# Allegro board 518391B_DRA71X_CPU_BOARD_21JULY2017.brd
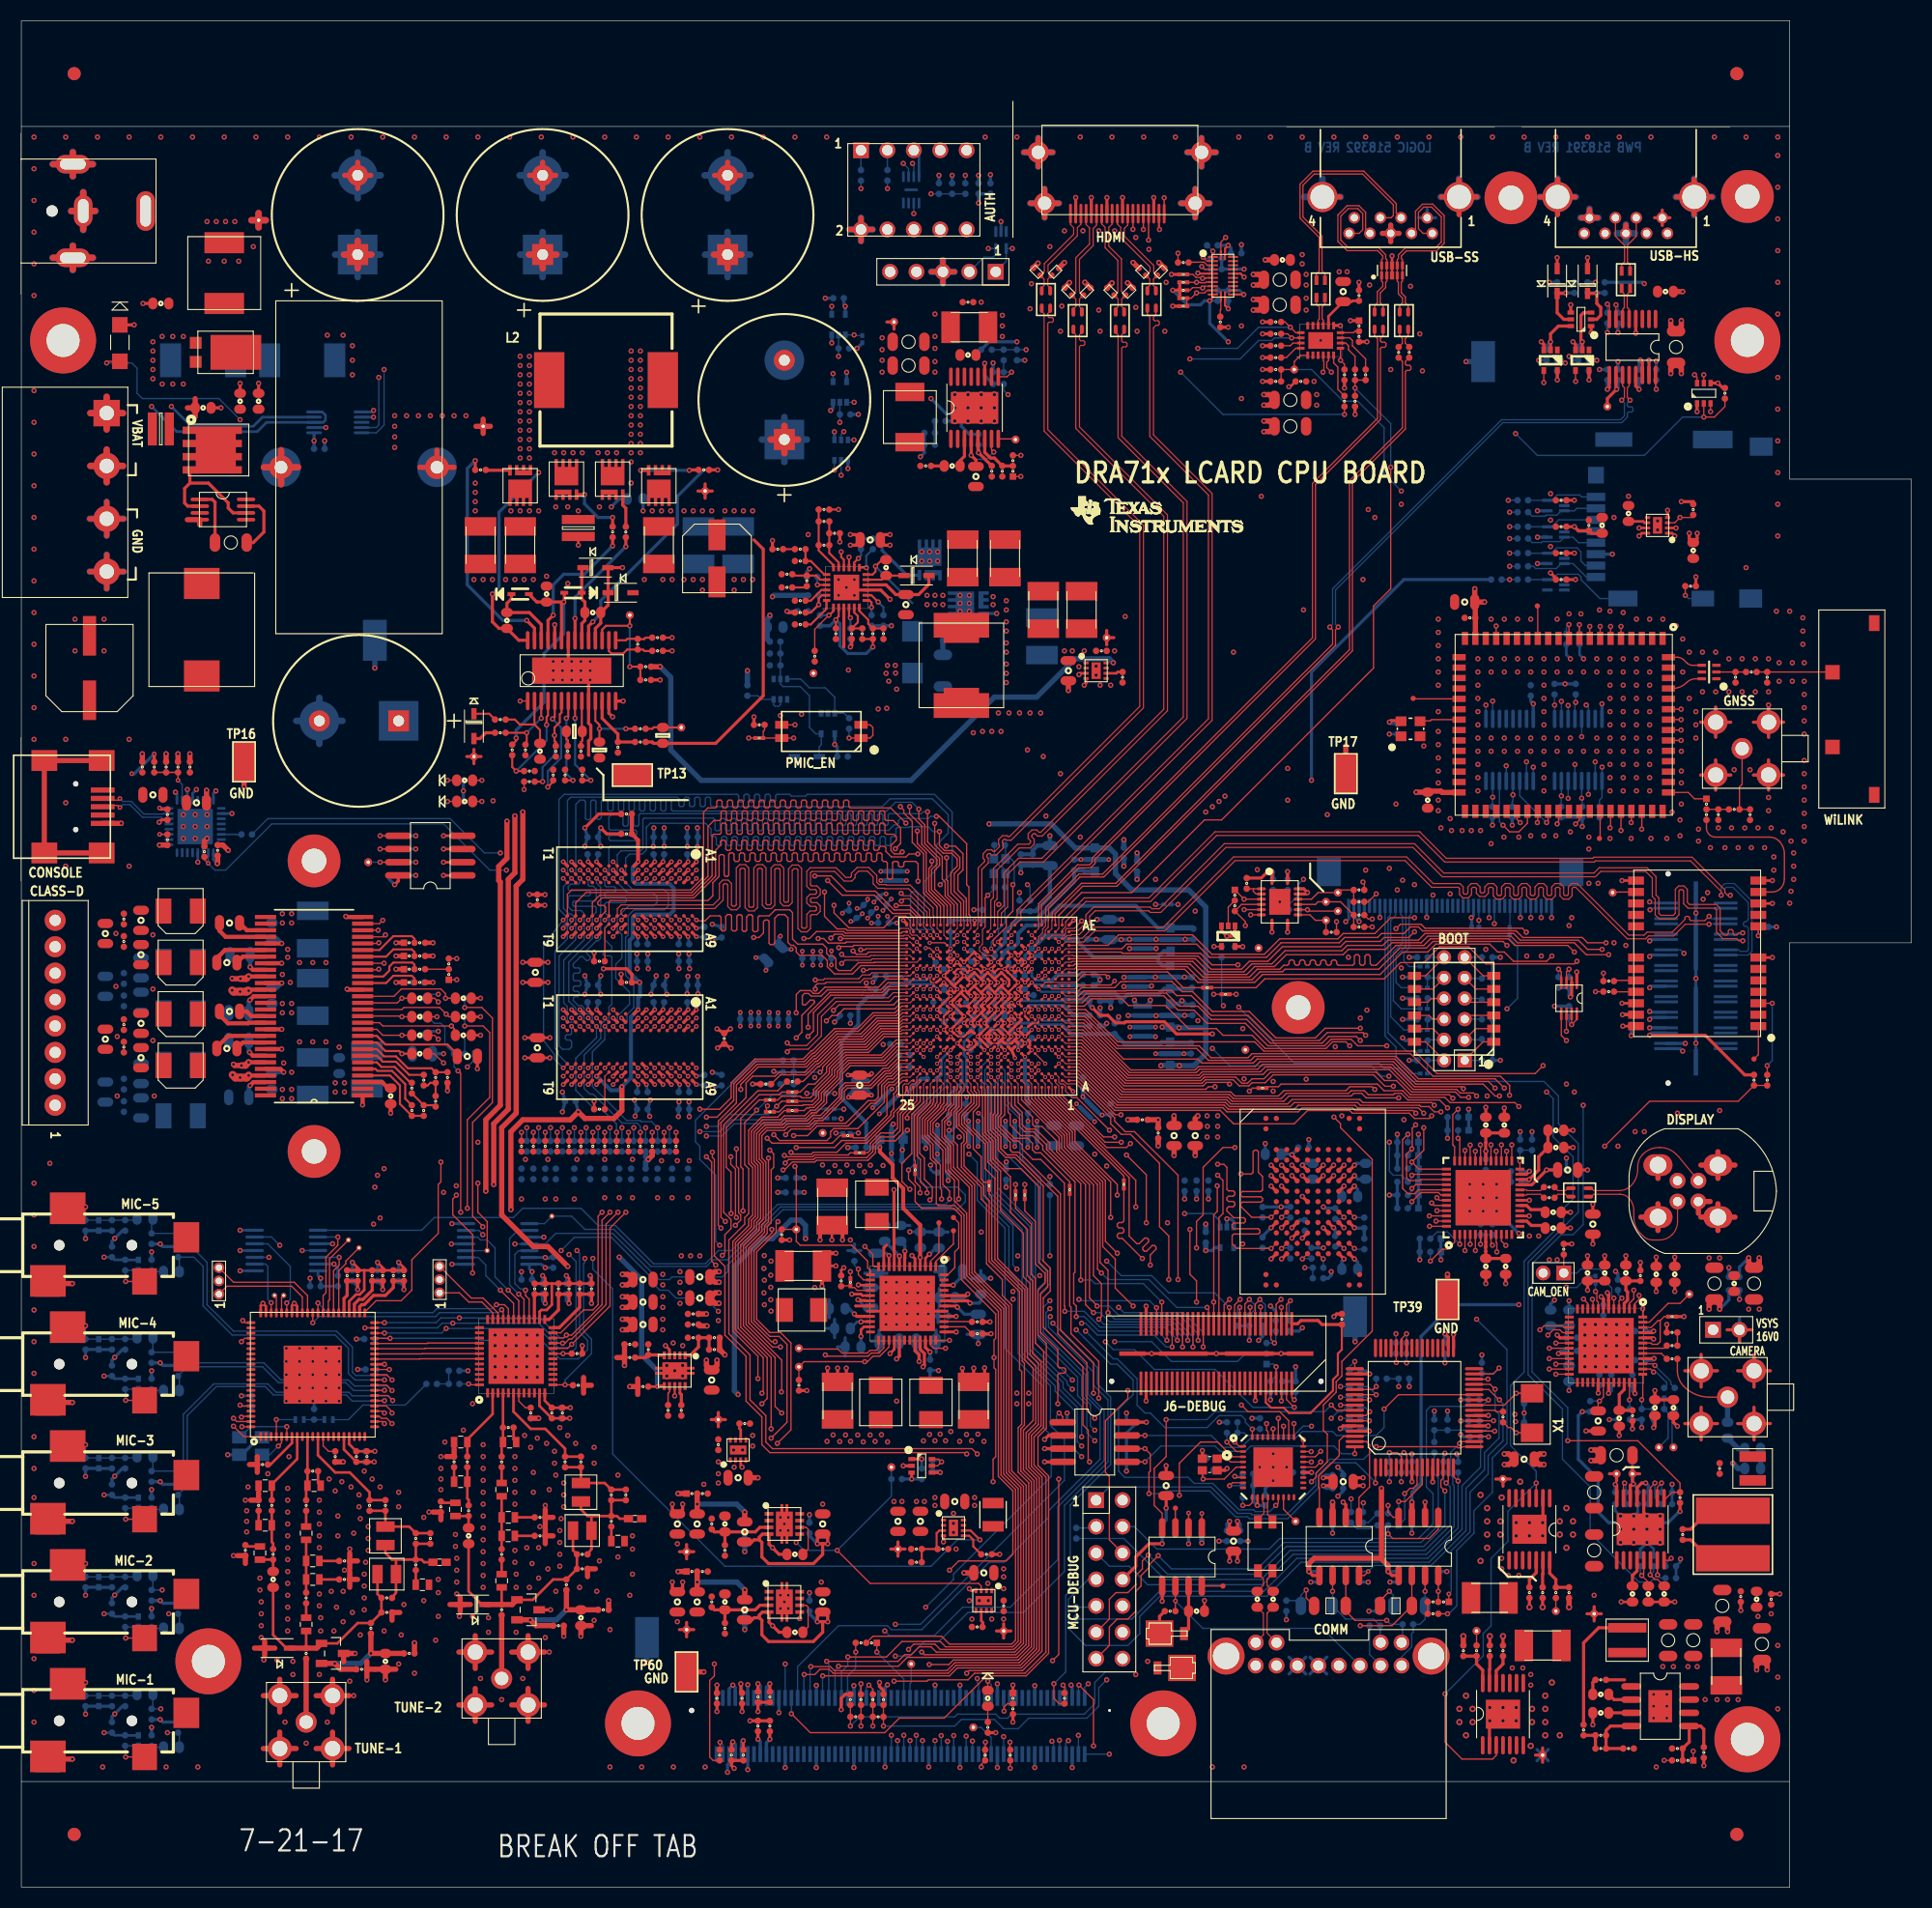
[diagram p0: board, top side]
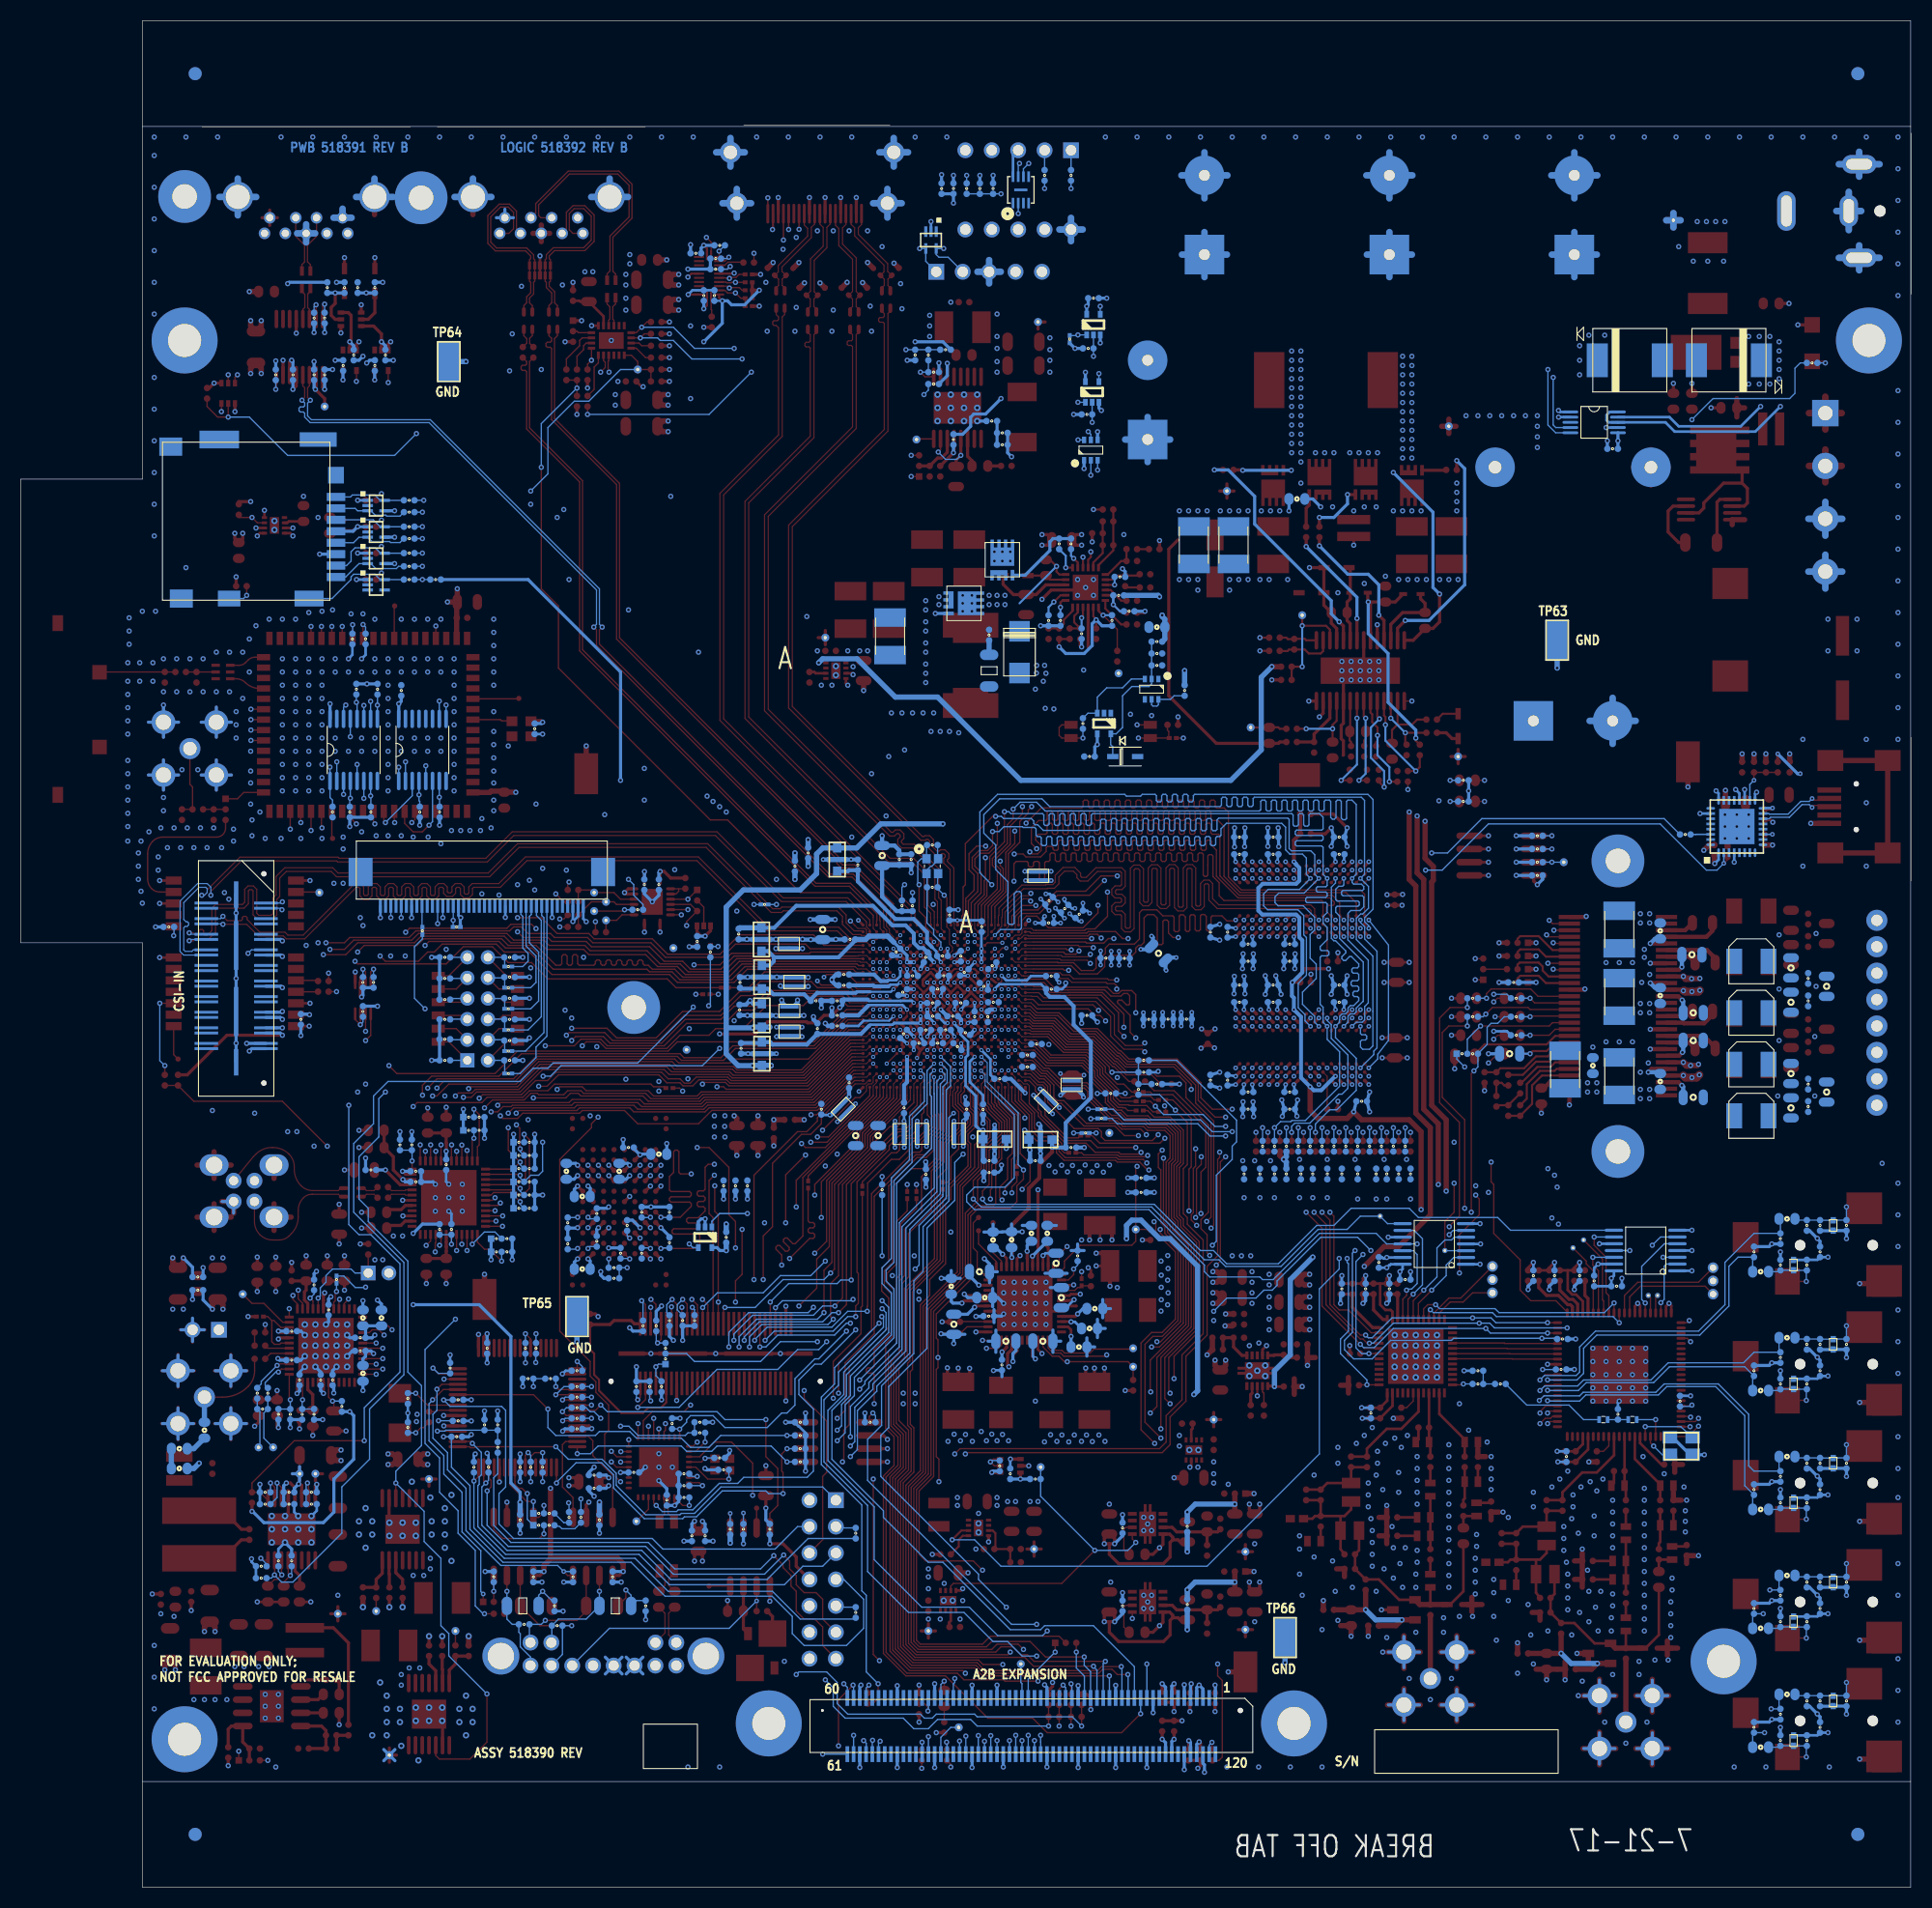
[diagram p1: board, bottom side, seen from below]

Outline 181.74 x 179.45 mm; copper layers: TOP, L2_GND, LY3, LY4, LY5_PWR, BOTTOM. Coordinates in mm from the lower left corner of the outline.
Outline path: 0.05,169.29 0.05,179.45 170.05,179.45 170.05,169.29 ; 0.05,169.29 170.05,169.29 ; 0.05,169.29 0.05,10.16 ; 170.05,169.29 170.05,135.38 181.74,135.38 181.74,90.8 170.05,90.8 170.05,10.16 ; 0.05,10.16 0.05,0 170.05,0 170.05,10.16 ; 0.05,10.16 170.05,10.16

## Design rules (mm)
net group CONN_USB2_DM: nets CONN_USB2_DM USB2_DM
net group CONN_USB2_DP: nets CONN_USB2_DP USB2_DP
net group DIFFPAIR15: nets H_USB2_DN H_USB2_DP
net group DIFFPAIR17: nets H_USB1_DN H_USB1_DP
net group DIFFPAIR18: nets CONN_USB1_DM CONN_USB1_DP
net group DIFFPAIR19: nets USB_AC_TXN0 USB_AC_TXP0
net group DIFFPAIR20: nets CONN_USB_TXN0 CONN_USB_TXP0
net group DIFFPAIR21: nets H_USB3_RXN H_USB3_RXP
net group DIFFPAIR22: nets CONN_USB_RXN0 CONN_USB_RXP0
net group DIFFPAIR28: nets H_USB3_TXN H_USB3_TXP
net group EMAC[1]_TXC: nets EMAC[1]_TXC N3026308320
net group H_MMC1_CLK: nets H_MMC1_CLK N27144522
net group HDMI_TX0+: nets H_HDMI_DY0 HDMI_TX0+
net group HDMI_TX0-: nets H_HDMI_DX0 HDMI_TX0-
net group HDMI_TX1+: nets H_HDMI_DY1 HDMI_TX1+
net group HDMI_TX1-: nets H_HDMI_DX1 HDMI_TX1-
net group HDMI_TX2+: nets H_HDMI_DY2 HDMI_TX2+
net group HDMI_TX2-: nets H_HDMI_DX2 HDMI_TX2-
net group HDMI_TXC+: nets H_HDMI_CLKY HDMI_TXC+
net group HDMI_TXC-: nets H_HDMI_CLKX HDMI_TXC-
net group USB1: nets USB1_DM USB1_DP
net group VOUT3B_CLK: nets N32593759 VOUT3B_CLK
net group CAM: nets CAM_D0 CAM_D1 CAM_D2 CAM_D3 CAM_D4 CAM_D5 CAM_D6 CAM_D7 CAM_HSYNC CAM_PCLK CAM_VSYNC
net group CSI: nets H_CSI2_DX0 H_CSI2_DX1 H_CSI2_DX2 H_CSI2_DY0 H_CSI2_DY1 H_CSI2_DY2
net group DATA_GRP0: nets H_DDR1_D0 H_DDR1_D1 H_DDR1_D2 H_DDR1_D3 H_DDR1_D4 H_DDR1_D5 H_DDR1_D6 H_DDR1_D7 H_DDR1_DQM0 H_DDR1_DQS0_N H_DDR1_DQS0_P
net group DATA_GRP1: nets H_DDR1_D8 H_DDR1_D9 H_DDR1_D10 H_DDR1_D11 H_DDR1_D12 H_DDR1_D13 H_DDR1_D14 H_DDR1_D15 H_DDR1_DQM1 H_DDR1_DQS1_N H_DDR1_DQS1_P
net group DATA_GRP2: nets H_DDR1_D16 H_DDR1_D17 H_DDR1_D18 H_DDR1_D19 H_DDR1_D20 H_DDR1_D21 H_DDR1_D22 H_DDR1_D23 H_DDR1_DQM2 H_DDR1_DQS2_N H_DDR1_DQS2_P
net group DATA_GRP3: nets H_DDR1_D24 H_DDR1_D25 H_DDR1_D26 H_DDR1_D27 H_DDR1_D28 H_DDR1_D29 H_DDR1_D30 H_DDR1_D31 H_DDR1_DQM3 H_DDR1_DQS3_N H_DDR1_DQS3_P
net group EMAC[1]_RX: nets EMAC[1]_RXC EMAC[1]_RXCTL EMAC[1]_RXD0 EMAC[1]_RXD1 EMAC[1]_RXD2 EMAC[1]_RXD3
net group EMAC[1]_TX: nets EMAC[1]_TXCTL EMAC[1]_TXD0 EMAC[1]_TXD1 EMAC[1]_TXD2 EMAC[1]_TXD3
net group FPD_DOUT+: nets FPD_DOUT+ N29842691 N32856854
net group FPD_DOUT-: nets FPD_DOUT- N29842700 N32867532
net group MMC2_CLK: nets MMC2_CLK N22073312 N32593135
net group PWR_PH: nets CS_P GND_EARTH N31573832 VAUDIO_9V0 VBAT_F VBAT_SYS VBUS1_5V0 VBUS2_5V0 VCAM_9V0 VCAP_VBBLDO_DSP VCAP_VBBLDO_GPU VCAP_VBBLDO_IVA VCAP_VBBLDO_MPU VCAP_VDDRAM_CORE1 VCAP_VDDRAM_CORE3 VCAP_VDDRAM_CORE4 VCAP_VDDRAM_DSP VCAP_VDDRAM_GPU VCAP_VDDRAM_IVA VCAP_VDDRAM_MPU VCC_APL VCC_LM5141 VCC_LM5175 VCNTL_3V3 VDA_MPU_ABE_FIL1V8 VDA_OSC_FIL1V8 VDA_PCIE_FIL1V8 VDA_PLL_1V8 VDA_SDIO_DV VDA_USB_3V3 VDD33_DSU921 VDD_1P1_CSI VDD_1P1_D VDD_1P1_FPD VDD_1P8 VDD_1P8_CSI VDD_1P8_FPD VDD_1V8_SW VDD_CORE_SW VDD_DDR_SW VDD_DSP_SW VDDA_LM5141 VDDI_MMC2 VDDIO_DSU921 VDDR_VREFSTL VDISP_16V0 VEXP_1V8A VEXP_1V8B VEXP_3V3A VEXP_3V3B VEXP_5V0A VEXP_5V0B VEXP_5V0C VEXP_5V0D VHDMI_5V0 VMEDIA_16V0 VOSNS VPOC_DISPLAY VSW_3V3 VSYS_5V0 VSYS_10V5 VTT_DDR VTUN_1V8 VTUN_1V8_OUT VTUN_3V3 VTUN_3V3_OUT VUSB_5V0
net group TRD1_N: nets N30512862 TRD1_N TRD_N
net group TRD1_P: nets N30512853 TRD1_P TRD_P
net group VOUT3B: nets VOUT3B_D0 VOUT3B_D1 VOUT3B_D2 VOUT3B_D3 VOUT3B_D4 VOUT3B_D5 VOUT3B_D6 VOUT3B_D7 VOUT3B_D8 VOUT3B_D9 VOUT3B_D10 VOUT3B_D11 VOUT3B_D12 VOUT3B_D13 VOUT3B_D14 VOUT3B_D15 VOUT3B_D16 VOUT3B_D17 VOUT3B_D18 VOUT3B_D19 VOUT3B_D20 VOUT3B_D21 VOUT3B_D22 VOUT3B_D23 VOUT3B_DE VOUT3B_HSYNC VOUT3B_VSYNC

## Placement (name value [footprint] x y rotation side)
ANT1  TE-2118016-1  [ANT-2118016]  178.69 122.3 270 top
C1  2200uF  [CAP300X630UP]  32.38 164.59 90 top
C2  2200uF  [CAP300X630UP]  50.16 164.59 90 top
C3  2200uF  [CAP300X630UP]  67.94 164.59 90 top
C4  0.1uF  [C603-35X45]  121.28 156.46 0 top
C5  10uF  [C1206-40X70]  121.03 154.56 180 top
C6  0.1uF  [C603-35X45]  158.12 153.42 180 top
C7  2.2uF  [C805-35X60]  127.13 153.42 90 top
C8  0.22uF  [C603-35X45]  13.46 152.27 180 top
C9  10uF  [C1206-40X70]  121.03 152.15 180 top
C10  0.01uF  [C402-25]  91.06 152.4 0 top
C11  10uF  [C1210-70X102]  91.19 149.99 180 top
C12  10uF  [C1206-40X70]  159.13 148.08 90 top
C13  0.1uF  [C402-25]  132.46 147.57 90 top
C14  0.1uF  [C402-25]  133.48 147.57 90 top
C15  10uF  [C1206-40X70]  85.34 148.59 0 top
C16  0.1uF  [C603-35X45]  91.06 147.32 0 top
C17  10uF  [C1206-40X70]  85.34 146.3 0 top
C18  0.1uF  [C402-25]  120.65 144.78 180 top
C19  0.1uF  [C402-25]  123.06 144.78 180 top
C20  10uF  [C1206-40X70]  122.05 143 180 top
C21  0.22uF  [C603-35X45]  21.08 142.88 90 top
C22  0.22uF  [C603-35X45]  22.86 142.88 90 top
C23  2200uF  [CAP300X630UP]  73.41 146.81 90 top
C24  0.22uF  [C603-35X45]  17.53 142.24 0 top
C25  10uF  [C1206-40X70]  122.05 140.46 180 top
C26  1uF  [C603-35X45]  89.53 136.65 180 top
C27  0.1uF  [C402-25RD]  93.34 136.14 270 top
C28  4.7uF  [C805-35X60]  91.82 135.64 90 top
C29  1uF  [C805-35X60]  81.66 129.54 0 top
C30  2.2uF 50V X7R  [C1206-40X70]  20.19 129.29 0 top
C31  10uF  [C1210-70X102]  44.2 129.03 270 top
C32  10uF  [C1210-70X102]  48.01 129.03 270 top
C33  10uF  [C1210-70X102]  61.34 129.03 270 top
C34  10uF  [C1210-70X102]  65.15 129.03 270 bottom
C35  10uF  [C1210-70X102]  68.96 129.03 270 bottom
C36  0.1uF  [C402-25]  77.22 129.03 180 top
C37  10uF  [C1210-70X102]  90.55 127.76 270 top
C38  10uF  [C1210-70X102]  94.61 127.76 270 top
C39  0.1uF  [C603-35X45]  83.19 126.87 270 top
C40  150pF  [C402-25]  73.66 126.24 180 top
C41  0.015uF  [C402-25]  73.66 124.97 0 top
C42  1uF  [C603-35X45]  50.55 124.33 90 top
C43  0.047uF  [C402-25]  74.93 123.7 0 top
C44  10uF  [C805-35X60]  138.81 123.57 180 top
C45  4.7uF  [C805-35X60]  85.09 123.32 270 top
C47  0.1uF  [C603-35X45]  54.99 122.55 180 top
C48  0.01uF  [C402-25]  74.93 122.55 0 top
C49  0.1uF  [C402-25]  139.32 122.05 180 top
C50  0.1uF  [C603-35X45]  46.74 121.79 270 top
C51  0.01uF  [C402-25]  74.93 121.41 0 top
C53  0.1uF  [C402-25]  78.36 120.52 270 top
C54  0.01uF  [C402-25]  79.88 120.52 90 top
C55  220pF  [C402-25]  59.31 119.51 90 top
C56  22uF  [C1210-70X102]  98.3 122.81 90 top
C57  0.1uF  [C402-25RD]  103.89 118.87 180 top
C58  220uF  [CAP-VS-F-8383]  6.6 117.22 180 top
C59  22uF  [C1210-70X102]  101.98 122.81 90 top
C60  4.7uF  [C805-35X60]  100.71 116.97 270 top
C61  0  [C402-25]  166.37 116.84 0 top
C62  1000pF  [C402-25]  105.92 116.33 270 top
C63  0.047uF  [C402-25RD]  60.07 116.08 180 top
C64  22uF  [C1210-70X102]  98.17 120.27 90 bottom
C65  2200uF  [CAP300X630UP]  28.7 112.14 180 top
C66  100pF  [C402-25]  57.4 109.6 90 top
C67  0.1uF  [C603-35X45]  49.91 109.22 270 top
C68  0.022uF  [C402-25]  52.58 109.22 270 top
C69  1000pF  [C402-25]  53.85 109.22 270 top
C70  100pF  [C402-25]  48.51 109.35 90 top
C71  0.1uF  [C402-25RD]  11.68 107.7 90 top
C72  4700pF  [C402-25RD]  13.97 107.7 90 top
C73  0.1uF  [C402-25RD]  16.26 107.7 90 top
C74  150pF  [C402-25]  52.32 106.93 90 top
C75  0.047uF  [C402-25]  53.97 106.93 90 top
C76  1000pF  [C402-25]  48.89 106.3 0 top
C77  1uF  [C603-35X45]  135.25 104.52 270 top
C78  4.7uF  [C805-35X60]  16.89 104.27 0 top
C79  0  [C402-25]  164.72 103.63 0 top
C80  0.47uF  [SM-7351-CAP-0402]  58.23 103.19 180 top
C81  0.1uF  [C402-25RD]  14.1 103.12 270 top
C82  0.47uF  [SM-7351-CAP-0402]  58.23 101.28 180 top
C83  0.1uF  [C402-25RD]  18.92 99.69 90 top
C84  0.47uF  [SM-7351-CAP-0402]  49.66 94.93 90 top
C85  0.01uF  [C402-25]  9.91 93.09 90 top
C86  1uF  [C805-35X60]  11.56 92.96 270 top
C87  2.2uF  [C805-35X60]  20.07 92.71 0 top
C88  1uF  [C805-35X60]  8.13 91.69 90 top
C89  10uF  [C805-35X60]  49.47 87.96 90 top
C90  0.01uF  [C402-25]  9.91 90.93 270 top
C91  0.47uF  [SM-7351-CAP-0402]  58.23 86.99 180 top
C92  1uF  [C805-35X60]  11.56 89.66 90 top
C93  2.2uF  [C805-35X60]  19.81 88.9 0 top
C94  NP  [C603-35X45]  38.35 85.47 0 top
C95  NP  [C603-35X45]  42.54 85.47 0 top
C96  0.47uF  [SM-7351-CAP-0402]  67.63 81.6 90 top
C97  2.2uF  [C805-35X60]  20.07 84.2 0 top
C98  10uF  [C805-35X60]  49.66 80.71 90 top
C99  NP  [C603-35X45]  38.35 83.69 0 top
C100  NP  [C603-35X45]  42.54 83.69 0 top
C101  1uF  [C805-35X60]  11.56 83.06 270 top
C102  0.01uF  [C402-25]  9.91 82.93 90 top
C103  NP  [C603-35X45]  38.35 81.91 0 top
C104  NP  [C603-35X45]  42.54 81.91 0 top
C105  1uF  [C805-35X60]  8.13 81.53 90 top
C106  0.01uF  [C402-25]  9.91 80.77 270 top
C107  2.2uF  [C805-35X60]  19.81 80.64 0 top
C108  10uF  [C805-35X60]  80.64 77.11 270 top
C109  NP  [C603-35X45]  38.35 80.14 0 top
C110  2.2uF  [C805-35X60]  42.93 79.88 0 top
C111  1uF  [C805-35X60]  11.56 79.76 90 top
C112  1uF  [C402-25]  39.88 77.85 270 top
C113  0  [C402-25]  38.73 77.6 270 top
C114  0.47uF  [SM-7351-CAP-0402]  107.82 73.79 180 top
C115  1uF  [C402-25]  37.59 76.83 90 top
C116  4.7uF  [C603-35X45]  140.84 73.28 90 top
C117  0.1uF  [C603-35X45]  35.56 76.07 90 top
C118  1uF  [SM-7351-CAP-0402]  109.35 72.52 270 top
C119  4.7uF  [C805-35X60]  110.87 72.26 270 top
C120  10uF  [C805-35X60]  112.9 72.26 270 top
C121  1uF  [C402-25]  37.59 74.68 270 top
C122  4.7uF  [C603-35X45]  147.57 71.12 0 top
C123  10uF  [C805-35X60]  148.72 68.96 0 top
C124  0.1uF  [C402-25]  146.94 67.31 0 top
C125  0.1uF  [C402-25]  146.94 66.29 0 top
C126  47uF  [C1210-70X102]  78.02 65.45 270 top
C127  4.7uF  [C603-35X45]  147.32 64.9 0 top
C128  10uF  [C805-35X60]  151.13 63.75 90 top
C129  4.7uF  [C603-35X45]  147.32 63.37 0 top
C130  47uF  [C1210-70X102]  75.22 59.74 0 top
C131  4.7uF  [C603-35X45]  140.84 59.69 270 top
C132  4.7uF  [C603-35X45]  142.75 59.69 270 top
C133  4.7uF  [C603-35X45]  152.27 59.05 90 top
C134  10uF  [C603-35X45]  154.31 59.05 270 top
C135  1uF  [C603-35X45]  157.23 58.93 270 top
C136  18pF  [C402-25]  31.37 58.8 90 top
C137  2.2nF  [C402-25]  32.38 58.8 90 top
C138  18pF  [C402-25]  33.78 58.8 90 top
C139  2.2nF  [C402-25]  34.8 58.8 90 top
C140  2.2nF  [C402-25]  35.81 58.8 90 top
C141  18pF  [C402-25]  36.83 58.8 90 top
C142  1000pF  [C402-25]  155.7 58.8 90 top
C143  10uF  [C805-35X60]  65.28 58.67 180 top
C144  10uF  [C805-35X60]  59.82 58.42 0 top
C145  10uF  [C1206-40X70]  162.81 58.04 270 top
C146  10uF  [C1206-40X70]  166.62 58.04 90 top
C147  18pF  [C402-25]  49.4 57.53 90 top
C148  2.2nF  [C402-25]  50.42 57.53 90 top
C149  18pF  [C402-25]  51.69 57.53 90 top
C150  2.2nF  [C402-25]  52.7 57.53 90 top
C151  18pF  [C402-25]  53.72 57.53 90 top
C152  2.2nF  [C402-25]  54.86 57.53 90 top
C153  10uF  [C805-35X60]  65.28 56.64 180 top
C154  10uF  [C805-35X60]  59.82 56.26 0 top
C155  0.1uF  [SM-7351-CAP-0402]  64.64 55.12 180 top
C156  10uF  [C805-35X60]  59.82 54.1 0 top
C157  1000pF  [C402-25]  64.64 54.1 180 top
C158  0.1uF  [SM-7351-CAP-0402]  58.55 52.2 0 top
C159  0.047uF  [C402-25RD]  158.75 52.07 0 top
C160  1000pF  [C402-25]  66.67 51.69 180 top
C161  10pF  [C402-25]  58.55 50.93 0 top
C162  0.1uF  [C402-25RD]  158.75 50.8 0 top
C163  10uF  [C805-35X60]  66.42 48.77 270 top
C164  0.1uF  [SM-7351-CAP-0402]  59.82 48.13 0 top
C165  47uF  [C1210-70X102]  78.52 46.78 90 top
C166  47uF  [C1210-70X102]  91.61 46.78 90 top
C167  10uF  [C603-35X45]  157.1 46.1 270 top
C168  0.1uF  [C402-25]  49.02 45.59 90 top
C169  18pF  [C402-25]  51.05 45.59 90 top
C170  2.2nF  [C402-25]  52.07 45.59 90 top
C171  1000pF  [C402-25]  154.94 45.34 270 top
C172  10uF  [C603-35X45]  153.67 45.08 90 top
C173  10uF  [C805-35X60]  151.64 44.83 270 top
C174  1000pF  [C402-25]  69.6 44.58 0 top
C175  43pF  [C402-25]  46.86 44.2 0 top
C176  0.1uF  [C402-25RD]  67.06 42.54 270 top
C177  10uF  [C1206-40X70]  153.42 41.53 180 top
C178  0.1uF  [C402-25]  30.23 41.4 90 top
C179  2.2nF  [C402-25]  32.26 41.4 90 top
C180  18pF  [C402-25]  33.27 41.4 90 top
C181  10uF  [C805-35X60]  144.53 41.15 0 top
C182  680pF  [C402-25]  41.66 40.89 90 top
C183  13pF  [C402-25]  42.93 40.89 270 top
C184  22pF  [C402-25]  46.23 40.89 270 top
C185  2200pF  [C402-25]  53.85 40.89 270 top
C186  1uF  [C402-25]  23.24 40.64 0 top
C187  43pF  [C402-25]  28.07 40 0 top
C188  4.7uF  [C805-35X60]  68.96 39.37 0 top
C189  10uF  [C805-35X60]  127.13 38.99 0 top
C190  10uF  [C805-35X60]  110.11 38.61 90 top
C191  10uF  [C1206-40X70]  151.26 37.97 270 top
C192  1pF  [C402-25]  56.77 37.72 270 top
C194  10uF  [C805-35X60]  89.79 37.08 180 top
C195  680pF  [C402-25]  22.86 36.7 90 top
C196  13pF  [C402-25]  24.13 36.7 270 top
C197  22pF  [C402-25]  27.43 36.7 270 top
C198  2200pF  [C402-25]  35.05 36.7 270 top
C199  36pF  [C402-25]  40.39 36.58 270 top
C200  11pF  [C402-25]  43.05 36.19 270 top
C201  470pF  [C402-25]  49.91 35.56 0 top
C202  7.0pF  [C402-25]  56.77 35.18 270 top
C203  10uF  [C805-35X60]  84.33 35.18 90 top
C204  10uF  [C805-35X60]  86.49 35.18 90 top
C205  10uF  [C805-35X60]  63.12 34.92 90 top
C206  0.47uF  [C603-35X45]  67.69 34.92 270 top
C207  10uF  [C805-35X60]  77.09 34.92 270 top
C208  10uF  [C805-35X60]  69.6 34.16 270 top
C209  20pF  [C603-35X45]  43.05 33.78 270 top
C210  43pF  [C402-25]  49.91 33.78 0 top
C211  1pF  [C402-25]  37.97 33.53 270 top
C212  10uF  [C805-35X60]  116.59 33.27 270 top
C213  36pF  [C402-25]  21.59 32.38 270 top
C214  10uF  [C1206-40X70]  151.26 32.38 90 top
C215  11pF  [C402-25]  24.26 32 270 top
C216  1nF  [C402-25]  46.23 32 270 top
C217  3.6pF  [C402-25]  53.97 32 180 top
C218  0.47uF  [C603-35X45]  74.42 32 180 top
C219  43pF  [C402-25]  31.11 31.37 0 top
C220  100pF  [C402-25]  86.11 31.24 0 top
C221  7.0pF  [C402-25]  37.97 30.99 270 top
C222  4.7uF  [C805-35X60]  92.58 30.23 180 top
C223  20pF  [C603-35X45]  24.26 29.59 270 top
C224  470pF  [C402-25]  31.11 29.59 0 top
C225  1uF  [C603-35X45]  154.94 28.19 270 top
C226  1uF  [C603-35X45]  156.46 28.19 270 top
C227  1uF  [C603-35X45]  157.99 28.19 270 top
C228  0.1uF  [C402-25RD]  165.35 27.94 270 top
C229  1nF  [C402-25]  27.43 27.81 270 top
C230  3.6pF  [C402-25]  35.18 27.81 180 top
C231  10uF  [C1210-70X102]  141.22 27.81 180 top
C232  0.1uF  [C603-35X45]  118.87 27.69 90 top
C233  0.1uF  [C603-35X45]  120.4 27.69 90 top
C234  0.1uF  [C402-25RD]  168.27 27.69 90 top
C235  10uF  [C805-35X60]  63.12 27.43 90 top
C236  0.47uF  [C603-35X45]  67.69 27.43 270 top
C237  10uF  [C805-35X60]  77.09 27.43 270 top
C238  0.1uF  [C402-25RD]  94.49 27.05 90 top
C239  10uF  [C1206-40X70]  163.58 27.05 270 top
C240  1uF  [C402-25]  46.23 26.67 270 top
C241  10uF  [C805-35X60]  69.6 26.67 270 top
C242  0.1uF  [C603-35X45]  113.03 26.54 0 top
C243  0.22uF  [C603-35X45]  53.85 25.91 270 top
C244  2.2nF  [C402-25]  51.69 25.15 0 top
C245  1000pF  [C402-25]  91.95 25.02 180 top
C246  0.47uF  [C603-35X45]  74.42 24.51 180 top
C247  10uF  [C1206-40X70]  158.37 23.75 270 top
C248  10uF  [C1206-40X70]  160.78 23.75 270 top
C249  10uF  [C1206-40X70]  167.39 23.37 270 top
C250  10uF  [C1210-70X102]  146.3 23.24 0 top
C251  1uF  [C402-25]  27.43 22.48 270 top
C252  0.22uF  [C603-35X45]  35.05 21.72 270 top
C253  10uF  [C1210-70X102]  163.96 21.21 90 top
C254  2.2nF  [C402-25]  32.77 20.95 0 top
C255  1uF  [C603-35X45]  151.89 18.54 180 top
C256  4.7uF  [C603-35X45]  151.89 16.76 180 top
C257  NP  [C402-25]  151.89 13.33 180 top
C258  0.1uF  [C402-25]  92.08 163.32 90 bottom
C259  0.1uF  [C402-25]  88.27 163.32 90 bottom
C260  0.1uF  [C402-25]  150.75 146.3 90 bottom
C261  0.1uF  [C402-25]  147.7 146.3 90 bottom
C262  47pF  [C402-25]  95.76 147.32 270 bottom
C263  0.1uF  [C402-25]  155.57 145.41 270 bottom
C264  1uF  [C402-25]  152.53 145.41 90 bottom
C265  470pF  [C402-25]  88.39 140.97 0 bottom
C266  0.1uF  [C603-35X45]  59.05 133.48 0 bottom
C267  0.1uF  [C402-25]  116.84 157.1 0 bottom
C268  0.1uF  [C402-25]  116.08 153.03 90 bottom
C269  0.1uF  [C402-25]  115.06 153.03 90 bottom
C270  1000pF  [C402-25]  88.65 120.4 90 bottom
C271  1000pF  [C402-25]  132.33 111.38 270 bottom
C272  0.47uF  [SM-7351-CAP-0402]  64.58 100.97 0 bottom
C273  0.47uF  [SM-7351-CAP-0402]  61.34 100.97 0 bottom
C274  0.47uF  [SM-7351-CAP-0402]  54.99 100.97 0 bottom
C275  0.1uF  [C402-25]  35.94 97.28 180 bottom
C276  10pF  [C402-25]  94.11 100.2 180 bottom
C277  0.1uF  [SM-7351-CAP-0402]  106.05 99.44 90 bottom
C278  0.1uF  [SM-7351-CAP-0402]  64.58 99.31 180 bottom
C279  0.1uF  [SM-7351-CAP-0402]  61.34 99.31 0 bottom
C280  0.1uF  [SM-7351-CAP-0402]  54.99 99.31 0 bottom
C281  10uF  [C805-35X60]  98.93 99.19 90 bottom
C282  0.1uF  [SM-7351-CAP-0402]  79.25 83.82 180 bottom
C283  0.1uF  [SM-7351-CAP-0402]  84.96 78.87 180 bottom
C284  1uF  [SM-7351-CAP-0402]  97.28 98.81 90 bottom
C285  0.1uF  [SM-7351-CAP-0402]  96.14 98.81 90 bottom
C286  1uF  [SM-7351-CAP-0402]  101.27 98.29 90 bottom
C287  0.1uF  [SM-7351-CAP-0402]  84.96 80.01 180 bottom
C288  0.1uF  [SM-7351-CAP-0402]  107.31 98.17 90 bottom
C289  1uF  [SM-7351-CAP-0508]  83.92 97.23 90 bottom
C290  0.1uF  [C402-25RD]  121.79 96.39 270 bottom
C291  0.1uF  [C402-25RD]  120.4 96.39 270 bottom
C292  10pF  [C402-25]  94.11 96.14 0 bottom
C293  0.47uF  [SM-7351-CAP-0402]  82.88 94.84 135 bottom
C294  0.47uF  [SM-7351-CAP-0402]  81.38 94.08 135 bottom
C295  0.47uF  [SM-7351-CAP-0402]  79.98 93.55 135 bottom
C296  0.1uF  [SM-7351-CAP-0402]  92.46 93.47 270 bottom
C297  0.47uF  [SM-7351-CAP-0402]  82.93 92.71 180 bottom
C298  0.1uF  [SM-7351-CAP-0402]  89.36 92.35 90 bottom
C299  0.47uF  [SM-7351-CAP-0402]  67.37 91.82 270 bottom
C300  0.1uF  [SM-7351-CAP-0402]  65.72 91.82 270 bottom
C301  1uF  [SM-7351-CAP-0402]  112.73 91.64 270.1 bottom
C302  1uF  [SM-7351-CAP-0402]  102.02 91.13 0 bottom
C303  1uF  [SM-7351-CAP-0508]  107.89 90.69 90 bottom
C304  0.1uF  [SM-7351-CAP-0402]  63.75 90.68 0 bottom
C305  0.1uF  [SM-7351-CAP-0402]  59.75 90.68 0 bottom
C306  0.1uF  [SM-7351-CAP-0402]  97.58 89.92 321.4 bottom
C307  10uF  [C805-35X60]  72.36 89.79 225 bottom
C308  0.1uF  [SM-7351-CAP-0402]  91.37 89.51 90 bottom
C309  0.1uF  [SM-7351-CAP-0402]  93.13 89.53 180 bottom
C310  0.1uF  [SM-7351-CAP-0402]  94.74 89.41 290.4 bottom
C311  0.47uF  [SM-7351-CAP-0402]  77.42 89.33 180 bottom
C312  0.47uF  [SM-7351-CAP-0402]  75.64 89.31 180 bottom
C313  0.47uF  [SM-7351-CAP-0402]  63.75 89.03 0 bottom
C314  0.47uF  [SM-7351-CAP-0402]  59.75 89.03 0 bottom
C315  0.47uF  [SM-7351-CAP-0402]  88.34 88.6 320 bottom
C316  10uF  [C1210-70X102]  28.07 92.07 270 bottom
C317  0.1uF  [C603-35X45]  24.13 91.95 90 bottom
C318  0.1uF  [SM-7351-CAP-0402]  96.01 87.63 181.1 bottom
C319  0.47uF  [SM-7351-CAP-0402]  91.03 87.96 322.7 bottom
C320  1uF  [SM-7351-CAP-0402]  102.62 87.76 360 bottom
C321  0.47uF  [SM-7351-CAP-0402]  93.01 87.63 180 bottom
C322  1uF  [SM-7351-CAP-0402]  82.67 87.6 180 bottom
C323  1uF  [SM-7351-CAP-0508]  107.38 87.04 90 bottom
C324  1uF  [SM-7351-CAP-0402]  112.6 86.98 90 bottom
C325  0.47uF  [SM-7351-CAP-0402]  89.15 86.61 40 bottom
C326  0.47uF  [SM-7351-CAP-0402]  64.58 86.74 0 bottom
C327  0.47uF  [SM-7351-CAP-0402]  61.34 86.74 0 bottom
C328  0.47uF  [SM-7351-CAP-0402]  54.99 86.74 0 bottom
C329  1uF  [SM-7351-CAP-0402]  102.61 86.71 0 bottom
C330  2.2uF  [C805-35X60]  21.08 89.66 0 bottom
C331  0.1uF  [SM-7351-CAP-0402]  82.67 86.35 180 bottom
C332  0.47uF  [SM-7351-CAP-0402]  93.6 86.36 180 bottom
C333  0.1uF  [SM-7351-CAP-0402]  105.29 85.22 180 bottom
C334  1uF  [SM-7351-CAP-0402]  103.25 83.82 0 bottom
C335  0.1uF  [SM-7351-CAP-0402]  88.24 85.09 0 bottom
C336  0.1uF  [SM-7351-CAP-0402]  64.58 85.09 180 bottom
C337  0.1uF  [SM-7351-CAP-0402]  61.34 85.09 0 bottom
C338  0.1uF  [SM-7351-CAP-0402]  54.99 85.09 0 bottom
C339  1uF  [C805-35X60]  11.56 88.39 270 bottom
C340  0.1uF  [SM-7351-CAP-0402]  94.09 85.01 180 bottom
C341  0.47uF  [SM-7351-CAP-0402]  91.38 85.03 180 bottom
C342  0.1uF  [SM-7351-CAP-0402]  96.95 86.06 145 bottom
C343  1uF  [SM-7351-CAP-0402]  112.64 84.34 270 bottom
C344  1uF  [SM-7351-CAP-0508]  107.85 84.26 270 bottom
C345  0.1uF  [SM-7351-CAP-0402]  103.25 85.22 0 bottom
C346  0.01uF  [C402-25]  9.91 87.38 90 bottom
C347  0.47uF  [SM-7351-CAP-0402]  94.08 83.74 180 bottom
C348  0.47uF  [SM-7351-CAP-0402]  92.15 83.74 180 bottom
C349  0.1uF  [SM-7351-CAP-0402]  90.04 83.69 90 bottom
C350  1uF  [C402-25]  38.23 86.99 180 bottom
C351  0.47uF  [SM-7351-CAP-0402]  71.45 83.46 180 bottom
C352  0.47uF  [SM-7351-CAP-0402]  69.67 83.46 180 bottom
C353  0.1uF  [C402-25]  154.81 83.44 270 bottom
C354  0.47uF  [SM-7351-CAP-0402]  73.3 83.44 180 bottom
C355  1uF  [C805-35X60]  8.13 86.61 90 bottom
C356  0.1uF  [SM-7351-CAP-0402]  88.77 83.69 90 bottom
C357  0.47uF  [SM-7351-CAP-0402]  96.88 82.04 309.4 bottom
C358  1uF  [SM-7351-CAP-0402]  103.25 82.81 0 bottom
C359  0.1uF  [SM-7351-CAP-0402]  105.16 82.55 90 bottom
C360  0.1uF  [C603-35X45]  24.13 85.72 270 bottom
C361  0.1uF  [SM-7351-CAP-0402]  92.84 82.42 180 bottom
C362  0.1uF  [SM-7351-CAP-0402]  94.74 82.42 0 bottom
C363  10uF  [C1210-70X102]  28.07 85.6 90 bottom
C364  0.47uF  [SM-7351-CAP-0402]  90.93 82.17 206.5 bottom
C365  0.01uF  [C402-25]  9.91 85.22 270 bottom
C366  1uF  [C805-35X60]  11.56 85.09 90 bottom
C367  0.47uF  [SM-7351-CAP-0402]  93.6 81.15 0 bottom
C368  0.47uF  [SM-7351-CAP-0402]  91.69 80.82 220 bottom
C369  0.1uF  [SM-7351-CAP-0402]  84.09 81.07 180 bottom
C370  0.47uF  [SM-7351-CAP-0402]  95.4 81.15 180 bottom
C371  2.2uF  [C805-35X60]  20.95 84.07 0 bottom
C372  1uF  [SM-7351-CAP-0402]  112.5 80.66 270 bottom
C373  1uF  [SM-7351-CAP-0508]  107.84 82.25 270 bottom
C374  1uF  [SM-7351-CAP-0402]  87.63 77.72 180 bottom
C375  1000pF  [C402-25]  73.79 78.36 0 bottom
C376  2.2uF  [C805-35X60]  20.95 81.41 0 bottom
C377  0.47uF  [SM-7351-CAP-0402]  67.37 77.6 270 bottom
C378  0.1uF  [SM-7351-CAP-0402]  65.72 77.6 270 bottom
C379  0.1uF  [SM-7351-CAP-0402]  102.11 77.34 270 bottom
C380  1uF  [SM-7351-CAP-0508]  80.72 77.14 270 bottom
C381  2.2uF  [C805-35X60]  38.61 80.14 0 bottom
C382  0.1uF  [SM-7351-CAP-0402]  63.75 76.45 0 bottom
C383  0.1uF  [SM-7351-CAP-0402]  59.75 76.45 0 bottom
C384  0.1uF  [C603-35X45]  30.61 78.99 270 bottom
C385  1uF  [SM-7351-CAP-0508]  83.15 75.58 315 bottom
C386  0.47uF  [SM-7351-CAP-0402]  52.83 75.56 180 bottom
C387  10uF  [C1210-70X102]  33.27 78.61 90 bottom
C388  1uF  [SM-7351-CAP-0402]  96.82 74.93 270 bottom
C389  1uF  [C805-35X60]  11.56 78.23 270 bottom
C390  0.1uF  [SM-7351-CAP-0402]  104.78 74.8 270 bottom
C391  0.47uF  [SM-7351-CAP-0402]  63.75 74.8 0 bottom
C392  0.47uF  [SM-7351-CAP-0402]  59.75 74.8 0 bottom
C393  1uF  [SM-7351-CAP-0508]  102.67 74.79 45 bottom
C394  1uF  [SM-7351-CAP-0402]  89.23 74.78 270 bottom
C395  1uF  [SM-7351-CAP-0402]  90.8 74.8 270 bottom
C396  10uF  [C1210-70X102]  28.07 77.98 90 bottom
C397  0.1uF  [C603-35X45]  24.13 77.47 270 bottom
C398  0.01uF  [C402-25]  9.91 77.22 90 bottom
C399  1uF  [C805-35X60]  8.13 76.45 90 bottom
C400  2.2uF  [C805-35X60]  20.95 75.95 0 bottom
C401  1uF  [SM-7351-CAP-0508]  91.58 72.44 180 bottom
C402  1uF  [SM-7351-CAP-0508]  95.12 72.44 180 bottom
C403  1uF  [SM-7351-CAP-0508]  97.26 72.42 180 bottom
C404  0.01uF  [C402-25]  9.91 75.06 270 bottom
C405  1uF  [C805-35X60]  11.56 74.93 90 bottom
C406  1uF  [SM-7351-CAP-0402]  80.77 71.12 180 bottom
C407  1uF  [SM-7351-CAP-0402]  84.2 69.85 180 bottom
C408  1uF  [SM-7351-CAP-0402]  88.65 69.85 180 bottom
C409  0.1uF  [C402-25]  140.84 69.47 270 bottom
C410  0.1uF  [C402-25]  143.76 68.83 180 bottom
C411  0.22uF  [C603-35X45]  127.76 66.42 0 bottom
C412  1uF  [SM-7351-CAP-0402]  88.65 68.71 0 bottom
C413  0.47uF  [SM-7351-CAP-0402]  64.13 68.58 270 bottom
C414  0.47uF  [SM-7351-CAP-0402]  62.61 68.58 270 bottom
C415  0.47uF  [SM-7351-CAP-0402]  61.21 68.58 270 bottom
C416  0.1uF  [SM-7351-CAP-0402]  60.07 68.58 270 bottom
C417  0.47uF  [SM-7351-CAP-0402]  58.67 68.58 270 bottom
C418  0.47uF  [SM-7351-CAP-0402]  57.53 68.58 270 bottom
C419  0.47uF  [SM-7351-CAP-0402]  56.13 68.58 270 bottom
C420  0.47uF  [SM-7351-CAP-0402]  54.74 68.58 270 bottom
C421  0.47uF  [SM-7351-CAP-0402]  53.21 68.58 270 bottom
C422  0.47uF  [SM-7351-CAP-0402]  51.43 68.58 270 bottom
C423  0.47uF  [SM-7351-CAP-0402]  50.42 68.58 270 bottom
C424  0.47uF  [SM-7351-CAP-0402]  49.28 68.58 270 bottom
C425  0.47uF  [SM-7351-CAP-0402]  48.13 68.58 270 bottom
C426  1uF  [SM-7351-CAP-0402]  94.72 68.54 270 bottom
C427  2.2uF  [C603-35X45]  127.76 59.44 0 bottom
C428  0.47uF  [SM-7351-CAP-0402]  74.04 68.2 180 bottom
C429  0.1uF  [C402-25]  143.76 67.82 180 bottom
C430  0.1uF  [SM-7351-CAP-0402]  114.17 67.44 270 bottom
C431  0.1uF  [SM-7351-CAP-0402]  113.03 67.44 270 bottom
C432  0.1uF  [SM-7351-CAP-0402]  111.89 67.44 270 bottom
C433  0.1uF  [C402-25]  123.32 71.12 0 bottom
C434  1uF  [SM-7351-CAP-0402]  74.04 66.8 180 bottom
C435  4.7uF  [C603-35X45]  124.21 68.83 270 bottom
C436  2.2uF  [C603-35X45]  120.4 70.48 180 bottom
C437  0.22uF  [C603-35X45]  129.29 68.83 270 bottom
C438  10uF  [C603-35X45]  11.94 64.26 180 bottom
C439  1000pF  [C402-25]  6.22 63.63 270 bottom
C440  2.2uF  [C603-35X45]  84.58 62.86 90 bottom
C441  2.2uF  [C603-35X45]  83.06 62.86 90 bottom
C442  0.1uF  [C402-25]  113.92 62.48 270 bottom
C443  2.2uF  [C603-35X45]  86.49 62.26 90 bottom
C444  2.2uF  [C603-35X45]  88.27 62.23 90 bottom
C445  0.1uF  [C402-25RD]  8.76 61.09 270 bottom
C446  0.1uF  [C402-25]  51.18 60.07 270 bottom
C447  10uF  [C805-35X60]  82.21 59.99 270 bottom
C448  1000pF  [C402-25]  10.03 59.82 270 bottom
C449  10uF  [C603-35X45]  14.48 59.18 180 bottom
C450  4.7uF  [C805-35X60]  89.57 59.18 180 bottom
C451  1uF  [C402-25]  36.32 58.8 90 bottom
C452  1uF  [C402-25]  34.29 58.8 90 bottom
C453  1uF  [C402-25]  31.88 58.8 90 bottom
C454  0.1uF  [C402-25RD]  164.72 58.67 0 bottom
C455  1000pF  [C402-25]  48.64 58.42 0 bottom
C456  1000pF  [C402-25]  30.48 58.29 270 bottom
C457  0.1uF  [C402-25]  28.32 57.78 0 bottom
C458  2.2uF  [C603-35X45]  92.29 57.78 90 bottom
C459  1uF  [C402-25]  54.74 57.53 90 bottom
C460  1uF  [C402-25]  52.45 57.53 90 bottom
C461  1uF  [C402-25]  50.16 57.53 90 bottom
C462  0.1uF  [C402-25RD]  164.72 57.4 180 bottom
C463  2.2uF  [C603-35X45]  89.07 56.69 180 bottom
C464  4.7uF  [C805-35X60]  81.7 56.69 90 bottom
C465  2.2uF  [C603-35X45]  78.49 55.63 180 bottom
C466  0.1uF  [C402-25RD]  152.15 55.5 270 bottom
C467  0.1uF  [SM-7351-CAP-0402]  88.68 54.91 180 bottom
C468  1uF  [C603-35X45]  148.84 54.74 270 bottom
C469  4.7uF  [C805-35X60]  92.04 54.12 270 bottom
C470  2.2uF  [C603-35X45]  78.99 53.72 180 bottom
C471  1000pF  [C402-25]  155.7 53.47 180 bottom
C472  1000pF  [C402-25]  149.1 52.83 0 bottom
C473  10uF  [C603-35X45]  11.94 52.83 180 bottom
C474  10uF  [C805-35X60]  87.03 52.5 0 bottom
C475  4.7uF  [C805-35X60]  83.48 52.5 180 bottom
C476  1000pF  [C402-25]  6.22 52.2 270 bottom
C477  2.2uF  [C603-35X45]  80.01 51.94 180 bottom
C478  0.1uF  [C402-25]  136.91 51.82 90 bottom
C479  1000pF  [C402-25]  149.1 51.56 0 bottom
C480  1000pF  [C402-25]  155.7 50.67 180 bottom
C481  0.1uF  [SM-7351-CAP-0402]  87.41 50.21 270 bottom
C482  0.1uF  [C402-25]  128.27 49.66 180 bottom
C483  6pF  [C402-25]  41.66 49.66 0 bottom
C484  0.1uF  [C402-25RD]  8.76 49.66 270 bottom
C485  10uF  [C603-35X45]  148.84 49.4 90 bottom
C486  1000pF  [C402-25]  154.94 48.77 90 bottom
C487  1000pF  [C402-25]  152.91 48.77 90 bottom
C488  0.1uF  [C402-25RD]  151.76 48.77 90 bottom
C489  1000pF  [C402-25]  10.03 48.39 270 bottom
C490  10uF  [C603-35X45]  14.48 47.75 180 bottom
C491  0.1uF  [C402-25RD]  159 47.5 270 bottom
C492  0.1uF  [C402-25RD]  157.99 47.5 270 bottom
C493  6pF  [C402-25]  144.53 46.99 270 bottom
C494  1uF  [C402-25]  51.94 45.59 90 bottom
C495  2pF  [C402-25]  28.19 45.47 90 bottom
C496  0.1uF  [C402-25]  139.7 44.83 180 bottom
C497  0.1uF  [C402-25]  106.81 44.7 180 bottom
C498  1000pF  [C402-25]  137.16 44.45 270 bottom
C499  6pF  [C402-25]  144.53 44.2 90 bottom
C500  0.1uF  [C402-25]  128.27 44.07 180 bottom
C501  1uF  [C402-25]  33.15 41.4 90 bottom
C502  10uF  [C603-35X45]  11.94 41.4 180 bottom
C503  10pF  [C402-25]  114.55 41.27 180 bottom
C504  1000pF  [C402-25]  6.22 40.77 270 bottom
C505  0.1uF  [C402-25]  133.73 40.39 270 bottom
C506  10pF  [C402-25]  114.17 40.13 0 bottom
C507  1000pF  [C402-25]  122.81 39.88 180 bottom
C508  0.01uF  [C402-25]  126.62 39.62 0 bottom
C509  100pF  [C402-25]  126.62 38.35 0 bottom
C510  0.1uF  [C402-25RD]  8.76 38.23 270 bottom
C511  1000pF  [C402-25]  119.63 37.21 90 bottom
C512  1000pF  [C402-25]  10.03 36.96 270 bottom
C513  10uF  [C603-35X45]  14.48 36.32 180 bottom
C514  0.1uF  [C402-25]  133.73 35.31 270 bottom
C515  0.1uF  [C402-25]  126.11 35.31 270 bottom
C516  0.1uF  [C402-25RD]  69.6 34.67 270 bottom
C517  0.1uF  [C402-25RD]  75.82 34.54 270 bottom
C518  0.01uF  [C402-25]  117.22 33.78 270 bottom
C519  100pF  [C402-25]  115.95 33.78 270 bottom
C520  10uF  [C603-35X45]  11.94 29.97 180 bottom
C521  0.1uF  [C402-25]  132.46 29.84 270 bottom
C522  0.1uF  [C402-25]  124.84 29.84 270 bottom
C523  1000pF  [C402-25]  6.22 29.34 270 bottom
C524  0.1uF  [C402-25RD]  69.6 27.18 270 bottom
C525  4700pF  [C402-25]  130.43 27.05 270 bottom
C526  4700pF  [C402-25]  121.67 27.05 270 bottom
C527  0.1uF  [C402-25RD]  75.82 27.05 270 bottom
C528  0.1uF  [C402-25RD]  8.76 26.8 270 bottom
C529  1000pF  [C402-25]  10.03 25.53 270 bottom
C530  10uF  [C603-35X45]  14.48 24.89 180 bottom
C531  10uF  [C603-35X45]  11.94 18.54 180 bottom
C532  1000pF  [C402-25]  6.22 17.91 270 bottom
C533  0.1uF  [C402-25RD]  8.76 15.37 270 bottom
C534  1000pF  [C402-25]  10.03 14.1 270 bottom
C535  10uF  [C603-35X45]  14.48 13.46 180 bottom
C536  10uF  [C805-35X60]  101.47 72.26 270 bottom
C537  10uF  [C805-35X60]  99.31 72.26 270 bottom
C538  120uF  [CAP-FK-D8-65X117]  66.93 127.76 0 top
C539  0.1uF  [C402-25]  145.16 115.06 270 bottom
C540  0.1uF  [C402-25]  150.75 130.94 90 top
C541  10uF  [C603-35X45]  152.02 130.94 90 top
C542  0.1uF  [C402-25]  148.08 133.35 180 top
C543  0.1uF  [C402-25]  148.08 125.73 180 top
C544  0.1uF  [C402-25]  148.08 128.27 180 top
C545  0.1uF  [C402-25]  148.08 130.81 180 top
C546  10uF  [C603-35X45]  160.78 128.52 270 top
C547  NP  [C603-35X45]  154.56 132.08 90 top
C548  0.1uF  [C402-25]  78.61 152.78 180 bottom
C549  0.1uF  [C402-25]  28.7 138.3 180 bottom
C550  0.1uF  [C402-25RD]  116.71 90.93 90 bottom
C551  10uF  [C805-35X60]  104.65 92.07 270 bottom
C552  0.22uF  [C603-35X45]  72.52 121.16 0 bottom
C553  150pF  [C402-25]  72.52 118.62 180 bottom
C554  NP-0.1uF  [C402-25]  78.99 108.71 180 bottom
D1  6.2V  [SOD323]  147.7 154.43 90 top
D2  6.2V  [SOD323]  150.62 154.43 90 top
D3  PDS5100H-13-01  [DIODE-POWERDI5]  19.69 147.57 0 top
D4  MMSZ5237BS-7-F  [SOD323]  55.24 126.87 0 top
D5  PMEG6010CEJ,115  [SOD323]  86.11 126.11 0 top
D6  BAS516,115  [SOD523]  53.09 124.46 0 top
D7  CUS05S40,H3F  [SOD323]  57.66 124.46 0 top
D8  BAS516,115  [SOD523]  48.01 124.33 180 top
D9  BAT54HT1G  [SOD323]  43.56 111.63 270 top
D10  LTST-C190KFKT  [LED603-35X45-REV]  42.67 106.43 0 top
D11  LTST-C190CKT  [LED603-35X45-REV]  42.67 104.39 0 top
D12  ESD DIODE  [ESD402]  59.05 35.43 0 top
D13  ESD DIODE  [ESD402]  40.26 31.24 0 top
D14  ESD DIODE  [SOD323]  43.43 27.18 180 top
D15  CM1213A-01SO  [SOT23-28X44]  48.77 26.67 270 top
D16  DIODE  [POWERMITE-CASE457-04]  109.47 24.38 0 top
D17  ESD DIODE  [SOD323]  24.64 22.99 180 top
D18  CM1213A-01SO  [SOT23-28X44]  29.97 22.48 270 top
D19  DIODE  [POWERMITE-CASE457-04]  111.63 21.08 180 top
D20  LTST-C190KFKT  [LED603-35X45-REV]  92.96 18.16 270 top
D21  SMCJ14A-13-F  [SMC-80X128]  27.05 146.81 180 bottom
D22  SMCJ30A-13-F  [SMC-80X128]  17.53 146.81 0 bottom
D23  B170-13-F  [SMA2-78SQ]  85.72 118.75 270 bottom
D24  NP-6.2V  [SOD323]  75.56 108.71 180 bottom
DPX1  DPX205950DT-9008A1  [DI-0805-6]  162.31 116.84 90 top
DS1  LED_GRN  [LED1206-59X59]  9.52 148.46 270 top
E1  80dB @ 27MHz  [EMI-NFM21P]  103.25 98.81 270 bottom
E2  80dB @ 27MHz  [EMI-NFM21P]  110.53 91.12 90 bottom
E3  80dB @ 27MHz  [EMI-NFM21P]  110.49 87.5 270 bottom
E4  80dB @ 27MHz  [EMI-NFM21P]  110.49 83.82 90 bottom
E5  80dB @ 27MHz  [EMI-NFM21P]  110.49 80.14 90 bottom
E6  80dB @ 27MHz  [EMI-NFM21P]  88.12 71.92 0 bottom
E7  80dB @ 27MHz  [EMI-NFM21P]  83.71 71.88 0 bottom
FB1  5 Ohm  [IND402-14X26]  29.59 44.96 180 bottom
FB2  5 Ohm  [IND402-14X26]  26.8 44.96 180 bottom
FL1  DLW21SN121HQ2  [EMI-36X15-DLW21]  154.31 154.56 90 top
FL2  DLW21SN121HQ2  [EMI-36X15-DLW21]  124.97 153.67 90 top
FL3  DLW21SN900HQ2  [EMI-36X15-DLW21-RDPADS]  98.55 152.65 90 top
FL4  DLW21SN900HQ2  [EMI-36X15-DLW21-RDPADS]  108.71 152.65 90 top
FL5  LW21SN900HQ2  [EMI-36X15-DLW21-RDPADS]  130.56 150.62 90 top
FL6  LW21SN900HQ2  [EMI-36X15-DLW21-RDPADS]  132.97 150.62 90 top
FL7  DLW21SN900HQ2  [EMI-36X15-DLW21-RDPADS]  101.6 150.62 90 top
FL8  DLW21SN900HQ2  [EMI-36X15-DLW21-RDPADS]  105.66 150.62 90 top
FL9  DLW21SN900HQ2  [EMI-36X15-DLW21-RDPADS]  149.86 66.8 0 top
J1  1932258-1-USB3  [CON-1932258]  131.7 159.77 180 top
J2  1932258-1-USB3  [CON-1932258]  154.31 159.77 180 top
J3  2214BR-10G  [CON-2214BR-10G]  80.77 167 180 top
J4  Phoenix Contacts - 1757268  [CONN4-MSTBA]  8.25 141.73 90 top
J6  FAKRA II  [CONN-ST-FAKRA]  165.48 109.47 270 top
J7  USBMINI_AB  [SAMTEC-MUSB]  7.87 103.89 270 top
J8  NP  [JUMP2X6-5432-2MM]  138.81 79.5 180 top
J9  1725711  [CONN-1725711]  3.3 75.18 90 top
J10  NP-2MM  [JUMP1X2-5635-2MM]  148.34 59.05 180 top
J11  NP-HDR3  [HPH1-3-4025]  40.26 57.15 90 top
J12  NP-HDR3  [HPH1-3-4025]  19.05 57.02 90 top
J13  NP  [JUMP1X2-6040]  162.69 53.59 90 top
J14  MIPI-QSH-030  [QSH-030-01-F]  114.94 51.31 180 top
J15  NP-3M 2514-6002  [JUMP2X7-6040]  103.38 37.21 0 top
J16  FAKRA II  [CONN-ST-FAKRA]  46.23 20.07 180 top
J17  Molex34826-0124  [MOLEX-34826-0124]  125.73 22.22 0 top
J18  FAKRA II  [CONN-ST-FAKRA]  27.43 15.87 180 top
J19  FX8-120P-SV1-91  [FX8-120P-SV1]  84.58 15.49 0 bottom
J20  PM5  [JUMP1X5-6040]  93.73 155.32 270 top
J21  FH12A-40S-0.5SH(55)  [FH12-40-SH]  137.41 94.36 270 bottom
J22  PJ-063BH  [PWRJACK-CUI-PJ063BH]  0 161.16 90 top
L1  3.3uH, 5A  [IND2-7030D]  19.56 155.19 90 top
L2  5.6uH - IHLP5050FDER5R6M01  [IND-IHLP5050]  56.26 144.91 0 top
L3  IHLP2020CZER2R2M01  [IND-IHLP2020]  85.47 141.35 90 top
L4  300uH  [IND2-ATCA-06]  32.51 136.52 0 top
L5  3.3uH, 9A  [IND-DFEG10040]  17.4 120.9 270 top
L6  2.2uH  [IND-IHLP-COMBO]  90.42 117.47 270 top
L7  NP  [L402-25]  164.85 116.33 90 top
L8  NP  [L402-25]  167.89 116.33 90 top
L9  BLM21PG221SN1  [L805-35X60]  12.7 105.03 0 top
L10  NP  [L402-25]  163.19 103.12 90 top
L11  NP  [L402-25]  166.24 103.12 90 top
L12  3.3uH  [IND2-FDSD0420]  15.37 93.85 180 top
L13  3.3uH  [IND2-FDSD0420]  15.37 88.9 180 top
L14  3.3uH  [IND2-FDSD0420]  15.37 83.95 180 top
L15  3.3uH  [IND2-FDSD0420]  15.37 78.99 180 top
L16  BLM18AG221SN1D  [L603-35X45]  142.62 73.28 270 top
L17  BLM18AG221SN1D  [L603-35X45]  147.57 72.77 0 top
L18  1.0uH  [IND2-65X90-IHLP1616]  82.3 65.66 270 top
L19  BLM18AG221SN1D  [L603-35X45]  159 58.93 90 top
L20  BLM18HE152SN1  [L603-35X45]  164.72 58.04 270 top
L21  1.0uH  [IND2-65X90-IHLP1616]  75.06 55.5 0 top
L22  1.0uH  [IND2-65X90-IHLP1616]  82.68 46.61 90 top
L23  1.0uH  [IND2-65X90-IHLP1616]  87.5 46.61 90 top
L24  BLM18AG221SN1D  [L603-35X45]  158.88 46.1 270 top
L25  68nH  [IND603-AISC-25X40]  42.29 42.8 0 top
L26  72nH  [IND603-AISC-25X40]  46.99 42.8 180 top
L27  4.7uH  [IND1515-40X100]  166.5 40.26 270 top
L28  39nH  [IND603-AISC-25X40]  42.29 38.99 0 top
L29  68nH  [IND603-AISC-25X40]  23.49 38.61 0 top
L30  72nH  [IND603-AISC-25X40]  28.19 38.61 180 top
L31  160nH  [IND603-AISC-25X40]  46.23 38.23 90 top
L32  1.5uH  [IND0805-40X70]  53.85 37.97 90 top
L33  62nH  [IND603-AISC-25X40]  41.78 36.32 270 top
L34  DFE252012PD-2R2M  [IND2520-40X80]  93.47 35.81 270 top
L35  100nH  [IND603-AISC-25X40]  46.86 35.56 180 top
L36  MPZ2012S102A  [L805-35X60]  65.02 34.92 270 top
L37  39nH  [IND603-AISC-25X40]  23.49 34.8 0 top
L38  1.0uH  [IND0805-40X70]  53.97 34.29 0 top
L39  160nH  [IND603-AISC-25X40]  27.43 34.04 90 top
L40  100uH  [IND-MSS7341]  164.59 33.91 270 top
L41  1.5uH  [IND0805-40X70]  35.05 33.78 90 top
L42  18nH  [IND603-AISC-25X40]  46.86 33.78 180 top
L43  330nH  [IND603-AISC-25X40]  57.4 33.27 180 top
L44  AE2002  [CHOKE4-AE2002]  119.63 32.77 90 top
L45  62nH  [IND603-AISC-25X40]  22.99 32.13 270 top
L46  18nH  [IND603-AISC-25X40]  28.07 31.37 180 top
L47  1.0uH  [IND0805-40X70]  35.18 30.1 0 top
L48  100nH  [IND603-AISC-25X40]  28.07 29.59 180 top
L49  72nH  [IND603-AISC-25X40]  46.23 29.46 90 top
L50  330nH  [IND603-AISC-25X40]  38.61 29.08 180 top
L51  BLM18HE152SN1  [L603-35X45]  166.88 27.69 270 top
L52  MPZ2012S102A  [L805-35X60]  65.02 27.43 270 top
L53  72nH  [IND603-AISC-25X40]  27.43 25.27 90 top
L54  XAL4020-222MEB  [COIL-XAL40]  154.43 23.75 90 top
L55  3.3uH  [IND2-FDSD0420]  15.37 89.03 180 bottom
L56  3.3uH  [IND2-FDSD0420]  15.37 84.07 180 bottom
L57  3.3uH  [IND2-FDSD0420]  15.37 79.12 180 bottom
L58  3.3uH  [IND2-FDSD0420]  15.37 74.17 180 bottom
L59  BLM18AG221SN1D  [L603-35X45]  147.07 54.74 90 bottom
L60  BLM18HE152SN1  [L603-35X45]  164.08 43.94 270 bottom
L61  0  [L603-35X45]  166.5 42.16 0 bottom
L62  0  [L603-35X45]  166.5 40.26 180 bottom
L63  BLM18AG221SN1D  [L603-35X45]  150.62 59.05 270 top
M1  -  [MHP125-250]  4.06 148.72 0 top
M2  -  [MHP125-250]  165.99 148.72 0 top
M3  -  [MHP125-250]  165.99 14.22 0 top
M4  -  [MHP125-250]  109.83 15.75 0 top
M5  -  [MHP125-250]  18.03 21.72 0 top
M6  -  [MHP125-250]  59.33 15.75 0 top
M9  -  [MHP93-200]  122.81 84.58 0 top
M10  -  [MHP93-200]  28.19 98.68 0 top
M11  -  [MHP93-200]  28.19 70.74 0 top
M12  -  [MHP93-200]  143.26 162.43 0 top
M13  -  [MHP93-200]  165.99 162.56 0 top
NOREF  -  []  170.05 0 90 top
NOREF#2  -  [unnamed#2]  5.13 174.37 0 top
NOREF#3  -  []  100.08 130.05 0 top
NOREF#4  -  []  0.05 179.45 0 top
NOREF#5  -  [unnamed#2]  164.97 5.08 0 top
NOREF#6  -  []  170.05 0 90 top
NOREF#7  -  []  -290.54 -209.11 0 top
NOREF#8  -  []  -290.54 -209.11 0 top
NOREF#9  -  []  0.05 179.45 0 top
NOREF#10  -  [unnamed#2]  164.97 174.37 0 top
NOREF#11  -  [unnamed#2]  5.13 5.08 0 top
NOREF#12  -  []  170.05 0 90 top
NOREF#13  -  []  170.05 0 90 top
NOREF#14  -  [unnamed#2]  164.97 5.08 180 bottom
NOREF#15  -  [unnamed#2]  5.13 174.37 180 bottom
NOREF#16  -  [unnamed#2]  164.97 174.37 180 bottom
NOREF#17  -  [unnamed#2]  5.13 5.08 180 bottom
P1  HDMI-RA-19-TYPEA  [HDMI-SMT-W-FLANGE-RDPADS]  105.66 160.91 180 top
P2  D4S10E-40MA5-C  [CON_D4S10E]  160.27 66.93 270 top
P3  STX-3500-4NTR  [ST_3500SM]  7.49 61.72 90 top
P4  STX-3500-4NTR  [ST_3500SM]  7.49 50.29 90 top
P5  FAKRA  [CONN-ST-FAKRA]  164.08 47.12 270 top
P6  STX-3500-4NTR  [ST_3500SM]  7.49 38.86 90 top
P7  STX-3500-4NTR  [ST_3500SM]  7.49 27.43 90 top
P8  STX-3500-4NTR  [ST_3500SM]  7.49 16 90 top
P9  QSH-020-01-L-D-DP-A  [QSH-020-DP-A]  161.04 87.38 270 bottom
P10  MicroSD_CARD  [MOLEX-49225-201]  162.18 129.79 270 bottom
Q1  BSS138PS  [SOT363-16X45]  149.99 150.75 90 top
Q2  BSS138PS  [SOT363-16X45]  161.8 143.64 0 top
Q3  SQJ422EP  [PWR-Q5A-SLPS319]  16.26 138.18 270 top
Q4  BSZ042N06NS  [TSDSON8]  52.45 135.38 0 top
Q5  BSZ035N03MS G  [TSDSON8]  56.9 135.38 0 top
Q6  BSZ042N06NS  [TSDSON8]  48.01 134.75 180 top
Q7  BSZ035N03MS G  [TSDSON8]  61.34 134.75 180 top
Q8  NX3008CBKS  [SOT363-16X45]  86.61 40.51 270 top
Q9  BSZ042N06NS  [TSDSON8]  87.38 127.63 180 bottom
Q10  BSZ042N06NS  [TSDSON8]  91.06 123.44 270 bottom
Q11  BSS138PS  [SOT363-16X45]  78.87 138.18 180 bottom
Q12  BSS138PS  [SOT363-16X45]  73.03 115.19 0 bottom
R1  4.99K  [R402-25]  128.65 153.03 270 top
R2  100K  [R402-25]  120.65 150.5 180 top
R3  100K  [R402-25]  120.65 149.35 180 top
R4  80.6K  [R402-25]  120.65 148.21 180 top
R5  19.1K  [R402-25]  120.65 147.07 180 top
R6  2K  [R402-25]  120.65 145.92 180 top
R7  100K  [R402-25]  127.25 145.41 90 top
R8  0  [R402-25]  128.27 145.41 90 top
R9  0  [R402-25]  129.29 145.41 90 top
R10  0  [R402-25]  127.25 142.88 90 top
R11  10K  [R402-25]  128.27 142.88 270 top
R12  0.010  [R0612]  13.46 140.21 270 top
R13  10K  [R402-25]  163.83 143.64 90 top
R14  3.01  [R402-25]  44.2 136.27 180 top
R15  0  [R402-25]  65.66 136.27 180 top
R16  0  [R402-25]  87 136.65 180 top
R17  10K  [R402-25]  94.36 136.14 270 top
R18  4.02K  [R402-25]  77.22 132.46 180 top
R19  0.008-PRL1632-R008-F-T1  [R0612]  53.59 130.68 180 top
R20  0  [R402-25]  56.9 130.3 270 top
R21  3.01  [R402-25]  58.17 130.3 90 top
R22  0  [R402-25]  78.23 130.18 0 top
R23  200  [R402-25]  72.77 128.65 180 top
R24  34.8K  [R402-25]  74.93 128.65 180 top
R25  240  [R402-25]  111.76 156.21 0 top
R26  20K  [R402-25]  74.93 127.51 0 top
R27  NP  [R201-6P6SPC]  111.76 155.07 180 top
R28  NP  [R201-6P6SPC]  111.76 154.31 180 top
R29  3.01K  [R402-25]  75.56 125.6 90 top
R30  NP  [R201-6P6SPC]  111.76 153.54 180 top
R31  NP  [R201-6P6SPC]  111.76 152.78 0 top
R32  NP  [R201-6P6SPC]  111.76 152.02 180 top
R33  10K  [R402-25]  115.32 150.5 90 top
R34  0  [R402-25]  80.9 120.52 270 top
R35  NP  [R402-25]  81.91 120.52 270 top
R36  0  [R402-25]  82.93 120.52 90 top
R37  100  [R402-25]  61.21 120.14 0 top
R38  100  [R402-25]  61.21 118.87 0 top
R39  10K  [R402-25]  76.33 118.36 90 top
R40  10K  [R402-25]  60.07 117.35 180 top
R41  10K  [R402-25]  70.99 111.76 180 top
R42  10  [R402-25]  46.1 112.27 0 top
R43  100K  [R402-25]  59.56 111.38 0 top
R44  3.16K  [R603-35X45]  53.21 111.12 0 top
R45  10  [R402-25]  46.1 111 0 top
R46  1.82K  [R603-35X45]  61.72 110.74 270 top
R47  10  [R402-25]  59.56 110.11 180 top
R48  NP  [R402-25]  47.24 109.35 90 top
R49  5.36K  [R603-35X45]  55.63 109.35 90 top
R50  110K  [R402-25]  51.43 109.22 270 top
R51  4.7K  [R402-25]  12.83 107.7 90 top
R52  10K  [R402-25]  15.11 107.7 90 top
R53  93.1K  [R402-25]  48.89 107.31 0 top
R54  0  [R402-25]  51.18 106.93 90 top
R55  10K  [R402-25]  14.1 100.71 90 top
R56  NP  [R402-25]  17.65 99.57 270 top
R57  100  [R402-25]  125.98 91.82 0 top
R58  100  [R402-25]  128.65 93.47 0 top
R59  1K  [R402-25]  117.86 96.52 270 top
R60  100  [R402-25]  128.65 92.33 0 top
R61  100  [R402-25]  128.65 94.74 0 top
R62  100  [R402-25]  128.65 95.88 0 top
R63  0  [R402-25]  115.44 89.92 270 bottom
R64  240  [R402-25]  55.63 89.03 180 top
R65  22  [R402-25]  152.65 87.12 180 top
R66  100  [R201-6P6SPC]  114.05 86.49 180 top
R67  22  [R402-25]  152.65 86.11 180 top
R68  2.2K  [R402-25]  166.62 77.6 270 top
R69  22  [R402-25]  167.89 77.6 90 top
R70  22  [R402-25]  74.17 77.47 180 top
R71  2.2K  [R402-25]  71.63 77.22 0 top
R72  0  [R201-6P6SPC]  74.17 76.45 180 top
R73  0  [R201-6P6SPC]  119.38 76.83 180 top
R74  0  [R201-6P6SPC]  72.01 75.69 180 top
R75  0  [R201-6P6SPC]  74.17 75.56 180 top
R76  240  [R402-25]  55.63 74.8 180 top
R77  0  [R201-6P6SPC]  74.17 74.68 180 top
R78  NP  [R402-25]  41.02 77.85 270 top
R79  0  [R201-6P6SPC]  72.01 74.55 180 top
R80  NP  [R402-25]  39.88 75.56 90 top
R81  100  [R201-6P6SPC]  79.5 72.26 180 top
R82  0  [R402-25]  38.73 74.68 90 top
R83  49.9  [SM-7351-RES-0402]  48.13 71.25 90 top
R84  49.9  [SM-7351-RES-0402]  49.28 71.25 90 top
R85  49.9  [SM-7351-RES-0402]  50.42 71.25 90 top
R86  49.9  [SM-7351-RES-0402]  51.56 71.25 90 top
R87  49.9  [SM-7351-RES-0402]  52.7 71.25 90 top
R88  49.9  [SM-7351-RES-0402]  53.85 71.25 90 top
R89  49.9  [SM-7351-RES-0402]  54.99 71.25 90 top
R90  49.9  [SM-7351-RES-0402]  56.13 71.25 90 top
R91  49.9  [SM-7351-RES-0402]  57.28 71.25 90 top
R92  49.9  [SM-7351-RES-0402]  58.42 71.25 90 top
R93  49.9  [SM-7351-RES-0402]  59.56 71.25 90 top
R94  49.9  [SM-7351-RES-0402]  60.71 71.25 90 top
R95  49.9  [SM-7351-RES-0402]  61.85 71.25 90 top
R96  49.9  [SM-7351-RES-0402]  62.99 71.25 90 top
R97  0  [R201-6P6SPC]  80.64 70.61 0 top
R98  0  [R201-6P6SPC]  85.98 68.96 90 top
R99  0  [R201-6P6SPC]  106.05 67.56 90 top
R100  0  [R201-6P6SPC]  93.09 67.44 90 top
R101  0  [R201-6P6SPC]  100.84 67.06 90 top
R102  0  [R201-6P6SPC]  95.63 66.55 90 top
R103  0  [R201-6P6SPC]  96.52 66.55 90 top
R104  2.2K  [R402-25]  73.15 62.74 90 top
R105  10K  [R402-25]  148.34 61.34 270 top
R106  DNP  [SM-7351-RES-0402]  78.87 58.29 270 top
R107  10K  [R201-6P6SPC]  79.76 58.17 270 top
R110  0  [R201-6P6SPC]  158.75 54.86 180 top
R112  10K  [SM-7351-RES-0402]  91.95 54.36 0 top
R114  49.9  [R402-25]  158.75 53.34 180 top
R115  10K  [SM-7351-RES-0402]  91.95 53.21 0 top
R117  10K  [R402-25]  64.64 52.83 180 top
R118  10K  [R402-25]  66.67 52.83 180 top
R120  10  [R402-25]  60.33 51.69 90 top
R122  10K  [R402-25]  53.47 51.31 0 top
R126  10K  [R402-25]  53.59 48.26 0 top
R127  10K  [R402-25]  74.8 48.26 270 top
R128  10K  [R402-25]  62.23 45.85 270 top
R129  100K  [R402-25]  63.5 45.85 270 top
R130  0  [R402-25]  142.49 45.21 90 top
R131  NP  [R402-25]  52.32 40.89 270 top
R132  2K  [R402-25]  163.32 40.26 270 top
R133  120  [R402-25]  58.17 37.72 270 top
R135  10K  [R402-25]  159.51 37.46 90 top
R136  NP  [R402-25]  33.53 36.7 270 top
R137  12.7K  [R402-25]  66.42 34.92 270 top
R138  2K  [R402-25]  159.77 33.91 270 top
R139  120  [R402-25]  39.37 33.53 270 top
R140  475K  [R402-25]  86.11 32.51 180 top
R141  150K  [R402-25]  88.65 32.51 180 top
R142  10K  [R402-25]  67.69 32.38 90 top
R143  475K  [R402-25]  92.84 32 0 top
R144  475K  [R402-25]  53.97 30.61 0 top
R145  475K  [R402-25]  52.45 29.08 270 top
R146  10K  [R402-25]  145.03 28.32 90 top
R147  0  [R402-25]  146.3 28.32 90 top
R148  10K  [R402-25]  147.57 28.32 90 top
R149  10K  [R402-25]  148.84 28.32 90 top
R150  31.6K  [R402-25]  66.42 27.43 270 top
R151  62  [R1206-40X70]  125.86 27.05 180 top
R152  62  [R1206-40X70]  132.21 27.05 0 top
R153  47K  [R402-25]  56.01 26.67 0 top
R154  1K  [R402-25]  110.49 26.54 0 top
R155  475K  [R402-25]  35.18 26.42 0 top
R156  475K  [R402-25]  33.66 24.89 270 top
R157  9.76K  [R402-25]  67.69 24.89 90 top
R158  10K  [R402-25]  138.68 22.73 270 top
R159  10K  [R402-25]  139.95 22.73 270 top
R160  0  [R402-25]  141.22 22.73 270 top
R161  10K  [R402-25]  142.49 22.73 270 top
R162  47K  [R402-25]  37.34 22.48 0 top
R163  0  [R402-25]  151.89 19.94 0 top
R164  0  [R402-25]  95.12 12.7 270 top
R165  0  [R402-25]  92.71 12.7 270 top
R166  NP  [R402-25]  69.47 12.7 90 top
R167  NP  [R402-25]  68.33 12.7 90 top
R168  NP  [R402-25]  67.18 12.7 270 top
R169  2.2K  [R402-25]  92.96 15.37 270 top
R170  0  [R402-25]  72.01 15.49 270 top
R171  0  [R402-25]  70.87 15.49 270 top
R172  51  [R402-25]  150.24 15.11 90 top
R173  0  [R402-25]  82.42 16.38 180 top
R174  0  [R402-25]  80.26 16.38 0 top
R175  95.3K  [R402-25]  151.89 14.6 180 top
R176  10K  [R402-25]  154.56 13.33 0 top
R177  3.32K  [R402-25]  159.26 13.33 180 top
R178  3.32K  [R402-25]  82.93 18.03 90 top
R179  0  [R402-25]  81.91 18.03 90 top
R180  0  [R402-25]  80.77 18.03 90 top
R181  3.32K  [R402-25]  79.76 18.03 90 top
R182  10K  [R402-25]  161.8 12.95 90 top
R183  0  [R201-6P6SPC]  115.82 85.85 180 top
R184  0  [R402-25]  100.33 18.16 270 top
R185  NP  [R402-25]  69.34 18.16 270 top
R186  NP  [R402-25]  66.93 18.16 270 top
R187  0  [R402-25]  72.01 18.29 270 top
R188  0  [R402-25]  70.87 18.29 270 top
R189  0  [R402-25]  93.22 163.32 270 bottom
R190  100  [R402-25]  90.8 163.32 270 bottom
R191  2.2K  [R402-25]  89.53 163.32 90 bottom
R192  0  [R402-25]  83.31 164.59 270 bottom
R193  0  [R402-25]  80.77 164.59 270 bottom
R194  680K  [R402-25]  152.27 153.8 270 bottom
R195  330K  [R402-25]  150.62 153.8 90 bottom
R196  680K  [R402-25]  149.35 153.8 270 bottom
R197  330K  [R402-25]  147.7 153.8 90 bottom
R198  10K  [R402-25]  153.54 150.88 90 bottom
R199  10K  [R402-25]  152.53 150.88 90 bottom
R200  47K  [R402-25]  149.73 147.32 90 bottom
R201  47K  [R402-25]  146.69 147.32 90 bottom
R202  1K  [R402-25]  9.52 146.56 0 bottom
R203  47  [R402-25]  92.84 147.83 0 bottom
R204  40.2K  [R402-25]  94.49 147.32 270 bottom
R205  158K  [R402-25]  157.23 145.41 90 bottom
R206  10K  [R402-25]  153.54 145.41 270 bottom
R207  10K  [R402-25]  93.98 145.67 180 bottom
R208  10K  [R402-25]  93.98 144.53 180 bottom
R209  3.01  [R402-25]  87.38 139.83 0 bottom
R210  3.0  [R402-25]  92.08 139.19 90 bottom
R211  3.01  [R402-25]  87.38 138.68 0 bottom
R212  NP  [R402-25]  114.55 157.86 0 bottom
R213  0  [R402-25]  81.91 129.16 270 bottom
R214  0  [R402-25]  80.77 129.16 90 bottom
R215  NP  [R402-25]  114.94 156.59 0 bottom
R216  10K  [R402-25]  114.94 155.57 180 bottom
R217  100K  [R402-25]  76.07 125.98 180 bottom
R218  10K  [R402-25]  76.2 124.21 180 bottom
R219  0  [R402-25]  82.93 121.79 90 bottom
R220  3.3  [R402-25]  81.79 121.79 270 bottom
R221  10K  [R402-25]  76.83 121.79 270 bottom
R222  42.2K  [R402-25]  79.76 120.52 90 bottom
R223  2.2K  [R402-25]  149.86 120.01 90 bottom
R224  2.2K  [R402-25]  148.59 120.01 90 bottom
R225  1.0  [R1206-40X70]  88.65 116.97 270 bottom
R226  NP  [R402-25]  149.48 115.19 270 bottom
R227  47K  [R402-25]  147.45 115.19 270 bottom
R228  47K  [R402-25]  143.38 103.38 90 bottom
R229  47K  [R402-25]  148.08 103.38 90 bottom
R230  47K  [R402-25]  141.48 103.38 90 bottom
R231  47K  [R402-25]  150.11 103.38 90 bottom
R232  22  [R402-25]  21.72 101.22 180 bottom
R233  3.32K  [R402-25]  35.94 101.09 0 bottom
R234  3.32K  [R402-25]  35.94 99.82 0 bottom
R235  10K  [R402-25]  35.94 98.55 0 bottom
R236  NP  [R402-25]  97.03 94.36 270 bottom
R237  10K  [R402-25]  96.01 94.36 90 bottom
R238  10K  [R402-25]  167.51 92.33 180 bottom
R239  2.2K  [R402-25]  43.05 106.43 180 bottom
R240  1K  [R402-25]  140.97 89.41 180 bottom
R241  10K  [R402-25]  134.75 89.41 180 bottom
R242  2.2K  [R402-25]  43.05 104.39 180 bottom
R243  10K  [R402-25]  134.75 87.5 180 bottom
R244  1K  [R402-25]  140.97 87.38 180 bottom
R245  2K  [R402-25]  148.84 86.99 90 bottom
R246  2K  [R402-25]  147.83 86.99 90 bottom
R247  10K  [R402-25]  134.75 85.47 180 bottom
R248  1K  [R402-25]  140.97 85.34 180 bottom
